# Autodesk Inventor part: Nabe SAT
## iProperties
Author: 42964
Shininess: 60.0
PropertySet Name: _Private Model Information
Length Units: 11269
Angle Units: 11283
Time Units: 11279
Mass Units: 11290
Length Display Precision: 3
Angle Display Precision: 2
Compacted: False
Created: 2000-11
Part Number: Nabe SAT
Document SubType Name: Modeling
Designer: 42964
Control State: 0
Master: False
Checked Out: False
PropertySet Name: Design Tracking Control
Density: 0.0
Volumn: 0.0
Area: 0.0
PropertySet Name: Model Information
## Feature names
1. Base1
